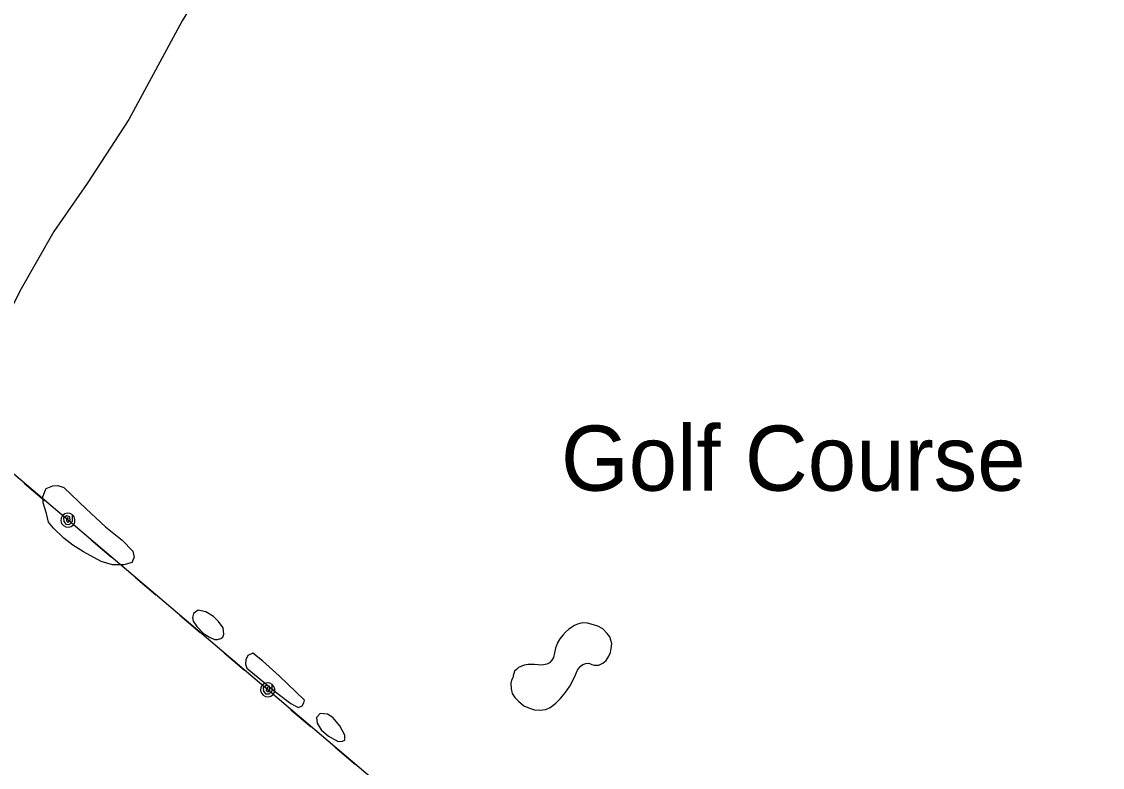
# Model space of a CAD drawing. Extents: x 3683402 to 3721514, y 487807 to 513565.
# Drawn here: x 3701526 to 3702904, y 501334 to 502284 of the extents above; entities that cross this region are included whole.
import ezdxf

# ---------------------------------------------------------------- set-up
doc = ezdxf.new("R2010")
doc.units = 0
for name, color, linetype in [('V-BLDG-IDEN', 7, 'Continuous'), ('V-TOPO-SHOR', 7, 'Continuous'), ('V-UTIL-LINE', 7, 'Continuous')]:
    doc.layers.add(name, color=color, linetype=linetype)

msp = doc.modelspace()

# ---------------------------------------------------------------- linework, layer by layer
at = {"layer": 'V-TOPO-SHOR'}
for p, q in [((3701667, 501595.1), (3701669.4, 501601.2)), ((3701833.2, 501469.7), (3701820.6, 501479.5))]:
    msp.add_line(p, q, dxfattribs=at)
for points in [[(3701830.9, 502461.4), (3701791.3, 502384.5), (3701730.7, 502285.1), (3701662.5, 502159.7), (3701609.5, 502077.9), (3701567.1, 502016.8), (3701525.5, 501943.9), (3701492.4, 501879.2), (3701462.1, 501828.3), (3701437.3, 501788.8), (3701434.2, 501783.9), (3701423.6, 501776.1), (3701389.1, 501771.1), (3701358.3, 501761.3), (3701330.3, 501751), (3701315.3, 501744.1), (3701299.9, 501731.8), (3701285.3, 501717.1), (3701268.4, 501698.2)], [(3701667, 501595.1), (3701656.4, 501591.9), (3701641.8, 501591.8), (3701627.2, 501596.2), (3701604.8, 501608.3), (3701591.3, 501616.8), (3701579.9, 501626.1), (3701566.5, 501638.7), (3701560.4, 501646.4), (3701557.5, 501657.3), (3701553.4, 501671.1), (3701552.9, 501678.5), (3701556.6, 501687.4), (3701557.4, 501689)], [(3701557.4, 501689), (3701565.9, 501692.7), (3701572, 501693.2), (3701579.7, 501690.3), (3701608.2, 501663.2), (3701633.1, 501640.5), (3701654.3, 501623.5), (3701667.8, 501609.4), (3701669.4, 501601.2)], [(3701750.9, 501534.1), (3701745.2, 501530), (3701743.6, 501524.7), (3701744.5, 501520.2), (3701749.4, 501513.3), (3701757.9, 501504.4), (3701765.3, 501499.6), (3701771.8, 501496.8), (3701775.8, 501496.8), (3701779.9, 501498), (3701782.3, 501499.6), (3701783.9, 501503.7), (3701782.7, 501511.8), (3701777, 501519.9), (3701770.4, 501526)], [(3701770.4, 501526), (3701760.7, 501532.1), (3701750.9, 501534.1)], [(3702152.7, 501450.5), (3702151.9, 501448.1), (3702150.3, 501444.8), (3702149.5, 501441.2), (3702149.9, 501433.9), (3702151.1, 501427.8), (3702154.8, 501422.9), (3702159.3, 501418), (3702166.2, 501412.4), (3702173.5, 501409.2), (3702179.6, 501407.1), (3702185.7, 501406.8), (3702190.2, 501407.2), (3702194.3, 501407.6), (3702199.5, 501410.1), (3702206.8, 501415.8), (3702212.5, 501421.1), (3702218.6, 501428.8), (3702224.6, 501437.4), (3702228.7, 501444.3), (3702231.9, 501451.6), (3702234.7, 501457.7), (3702238.4, 501462.6), (3702241.2, 501465.1), (3702245.3, 501466.3), (3702248.9, 501466.7), (3702253, 501465.1), (3702255.8, 501463.9), (3702261.9, 501463.9), (3702266.8, 501466.4), (3702270.9, 501470), (3702274.5, 501475.7), (3702276.5, 501480.2), (3702277.3, 501485.1), (3702278.1, 501491.6), (3702275.6, 501500.1), (3702272.4, 501504.6), (3702266.7, 501510.2), (3702260.5, 501513.9), (3702254.9, 501515.5), (3702247.1, 501517.5), (3702240.6, 501517.9), (3702234.5, 501516.2), (3702230.5, 501514.6), (3702223.6, 501510.1), (3702219.1, 501506), (3702215.9, 501502.4), (3702211.8, 501497.5), (3702209, 501492.6), (3702206.6, 501485.7), (3702205.4, 501479.6), (3702203.8, 501473.9), (3702201.8, 501470.6), (3702198.9, 501466.9), (3702195.3, 501465.3), (3702189.2, 501464.1), (3702179.9, 501464.8), (3702171.7, 501464.8), (3702166.4, 501464), (3702159.5, 501461.1), (3702156.7, 501458.7), (3702154.3, 501456.2), (3702152.7, 501450.5)], [(3701820.6, 501479.5), (3701814.5, 501476.2), (3701811.7, 501470.9), (3701811.3, 501465.2), (3701812.9, 501460.3), (3701851.6, 501428.4), (3701869.2, 501415.4), (3701878.5, 501410.2), (3701883.4, 501412.2), (3701885.8, 501415.9), (3701886.6, 501419.5), (3701854.4, 501450.3), (3701841.4, 501462), (3701833.2, 501469.7)], [(3701906.6, 501402.5), (3701901.7, 501397.2), (3701902.6, 501390.3), (3701907.9, 501381.8), (3701917.3, 501373.7), (3701929.5, 501366.9), (3701934.8, 501367.3), (3701938, 501368.5), (3701938, 501375), (3701931.4, 501386.8)], [(3701931.4, 501386.8), (3701922.5, 501397.3), (3701915.9, 501401.4), (3701906.6, 501402.5)]]:
    msp.add_lwpolyline(points, dxfattribs=at)
at = {"layer": 'V-UTIL-LINE'}
for points in [[(3706129.3, 497801), (3705828.8, 498068.5), (3705518.6, 498319.6), (3705215.1, 498577.2), (3704915.9, 498836.9), (3704693.9, 499026.2), (3704157.4, 499474.5), (3703735.3, 499831.2), (3703393.2, 500117.5), (3703044.2, 500410.8), (3702715.6, 500698.6), (3702052.3, 501252), (3701362.7, 501837.6), (3700635.7, 502454.8), (3700242, 502777.1), (3699904.9, 503059.6), (3699655.4, 503213.4), (3699371.4, 503385.3)], [(3701529.4, 501696.1), (3701555.3, 501674)], [(3701585, 501648.8), (3701585.3, 501651.7), (3701583.3, 501650.5), (3701583.1, 501647.8), (3701585.5, 501646.2), (3701587.8, 501648.6), (3701587.6, 501653.3), (3701583.4, 501654.5), (3701579.4, 501651.7), (3701579.6, 501647.2), (3701582.3, 501643.6), (3701587.1, 501643.5), (3701590.9, 501647.5), (3701590.8, 501655.7), (3701587.8, 501657.4), (3701584.3, 501657.8), (3701580.9, 501656.8), (3701578.2, 501654.6), (3701576.5, 501651.6), (3701576.1, 501648.1), (3701577, 501644.7), (3701579.2, 501641.9), (3701582.3, 501640.2), (3701585.8, 501639.8), (3701589.1, 501640.8), (3701591.9, 501643), (3701593.6, 501646), (3701594, 501649.5), (3701593, 501652.9), (3701590.8, 501655.7)], [(3701614.7, 501623.6), (3701640.7, 501601.5)], [(3701671.1, 501575.7), (3701697.1, 501553.6)], [(3701727.5, 501527.8), (3701753.5, 501505.7)], [(3701784, 501479.8), (3701809.9, 501457.8)], [(3701839.6, 501432.6), (3701839.9, 501435.5), (3701837.9, 501434.3), (3701837.6, 501431.6), (3701840.1, 501429.9), (3701842.4, 501432.4), (3701842.1, 501437.1), (3701838, 501438.3), (3701834, 501435.5), (3701834.1, 501430.9), (3701836.8, 501427.4), (3701841.7, 501427.3), (3701845.5, 501431.3), (3701845.4, 501439.5), (3701842.4, 501441.2), (3701838.9, 501441.6), (3701835.5, 501440.6), (3701832.7, 501438.4), (3701831, 501435.4), (3701830.6, 501431.9), (3701831.6, 501428.5), (3701833.8, 501425.7), (3701836.8, 501424), (3701840.3, 501423.6), (3701843.7, 501424.6), (3701846.5, 501426.8), (3701848.2, 501429.8), (3701848.6, 501433.3), (3701847.6, 501436.7), (3701845.4, 501439.5)], [(3701869.3, 501407.3), (3701895.2, 501385.3)], [(3701925.7, 501359.4), (3701951.6, 501337.4)]]:
    msp.add_lwpolyline(points, dxfattribs=at)

# ---------------------------------------------------------------- texts
at = {"layer": 'V-BLDG-IDEN'}
msp.add_text('Golf Course', height=83, dxfattribs=at).set_placement((3702213.5, 501686.4))

doc.saveas('drawing.dxf')
